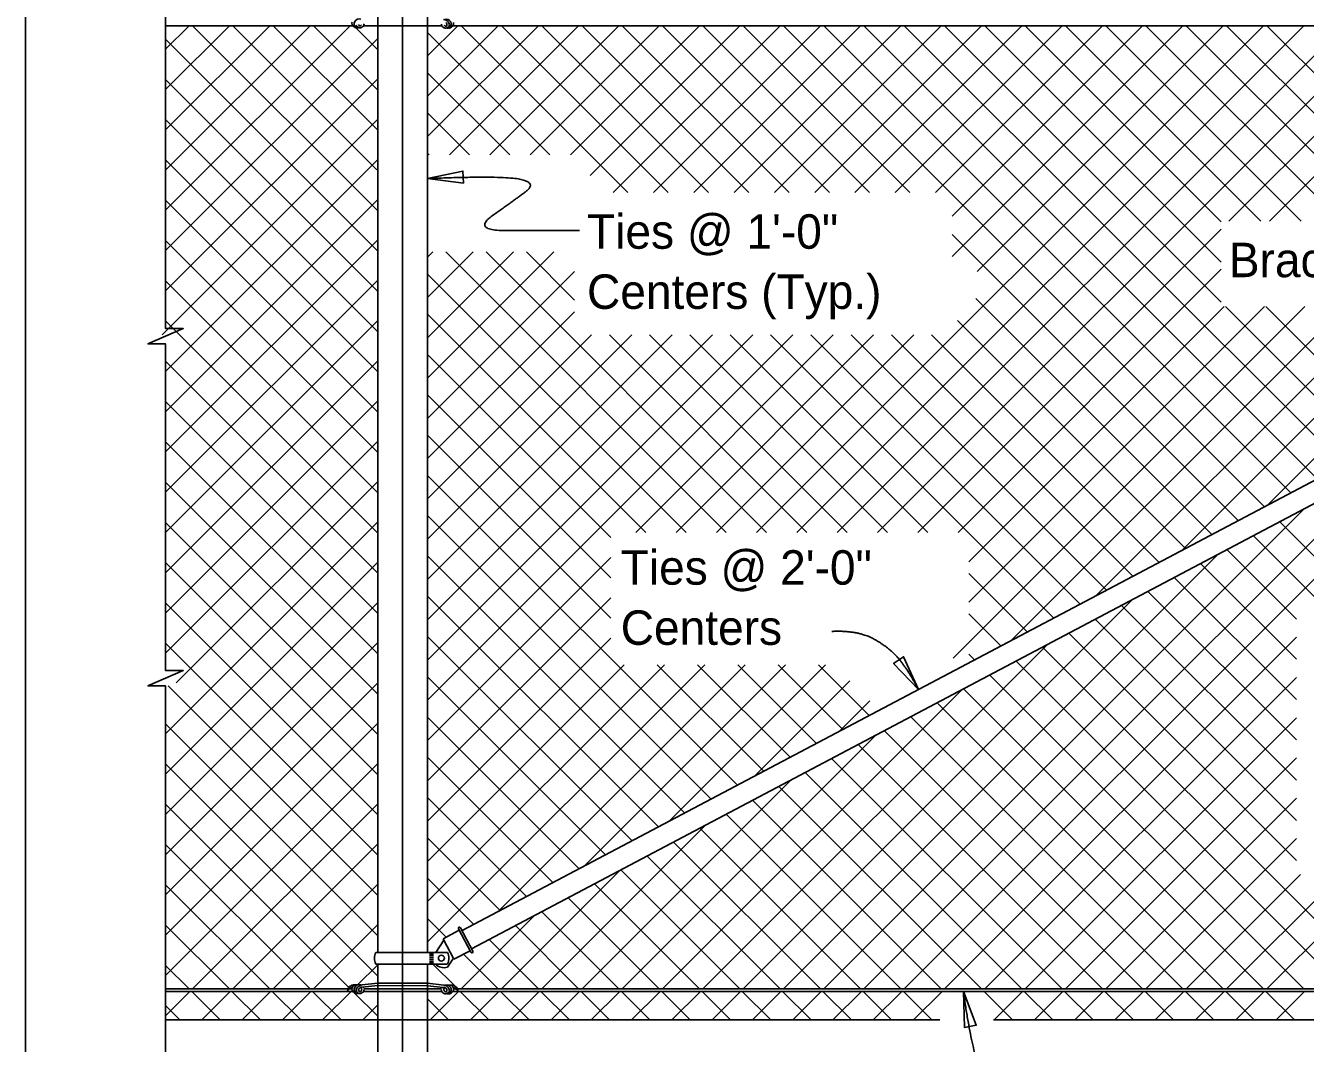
# Model space of a CAD drawing. Extents: x 0 to 41.2, y 0 to 26.
# Drawn here: x 0 to 7.49, y 17 to 22.96 of the extents above; entities that cross this region are included whole.
import ezdxf

# ---------------------------------------------------------------- set-up
doc = ezdxf.new("R2010")
doc.units = 0
for name, color, linetype in [('ActivePts-ConstElements', 7, 'Continuous'), ('CL_Major', 7, 'Continuous'), ('Dimension', 7, 'Continuous'), ('Miscellaneous', 7, 'Continuous'), ('Miscellaneous1', 7, 'Continuous'), ('SteelMisc', 7, 'Continuous'), ('SteelMisc_h', 7, 'Continuous'), ('SupstrConc', 7, 'Continuous'), ('TextStructures', 7, 'Continuous')]:
    doc.layers.add(name, color=color, linetype=linetype)

msp = doc.modelspace()

# ---------------------------------------------------------------- linework, layer by layer
at = {"layer": 'ActivePts-ConstElements'}
msp.add_lwpolyline([(0, 0), (41.2106, 0), (41.2106, 25.96), (0, 25.96)], close=True, dxfattribs=at)
at = {"layer": 'CL_Major'}
msp.add_line((2.2062, 25.5043), (2.2062, 14.6639), dxfattribs=at)
at = {"layer": 'Dimension'}
for points in [[(0.8194, 23.1382), (0.8194, 21.1819), (0.9227, 21.1819), (0.8194, 21.1369), (0.716, 21.0919), (0.8194, 21.0919), (0.8194, 20.1983)], [(0.8194, 20.1983), (0.8194, 19.1806), (0.9227, 19.1806), (0.8194, 19.1356), (0.716, 19.0906), (0.8194, 19.0906), (0.8194, 16.8862)], [(0.8194, 17.1362), (0.8194, 15.2854), (0.9227, 15.2854), (0.8194, 15.2404), (0.716, 15.1954), (0.8194, 15.1954), (0.8194, 13.3576)]]:
    msp.add_lwpolyline(points, dxfattribs=at)
for points in [[(2.3519, 22.0601), (2.5585, 22.1039), (2.5614, 22.0334)], [(5.2237, 19.0693), (5.1367, 19.2617), (5.0782, 19.2224)], [(5.4878, 17.3029), (5.4928, 17.0917), (5.5621, 17.1051)]]:
    msp.add_lwpolyline(points, close=True, dxfattribs=at)
for points in [[(3.2402, 21.7554), (3.0279, 21.7554), (2.6079, 21.7554), (2.8581, 21.9325), (2.9953, 22.0352), (2.7847, 22.0777), (2.352, 22.06)], [(4.7176, 19.4097), (4.8713, 19.4171), (5.0618, 19.3098), (5.1749, 19.1668), (5.2237, 19.0692)], [(6.1508, 16.5088), (5.753, 16.5088), (5.549, 16.8458), (5.4877, 17.3027)]]:
    msp.add_open_spline(points, degree=2, dxfattribs=at)
at = {"layer": 'Miscellaneous'}
for p, q in [((1.8998, 22.9547), (0.8192, 21.8742)), ((1.6641, 22.9547), (0.8192, 22.1099)), ((1.1927, 22.9547), (0.8192, 22.5813)), ((1.4284, 22.9547), (0.8192, 22.3456)), ((0.957, 22.9547), (0.8192, 22.817)), ((2.0603, 21.871), (0.9766, 22.9547)), ((2.0559, 22.1112), (1.2123, 22.9547)), ((2.0603, 22.3424), (1.448, 22.9547)), ((2.0603, 22.5781), (1.6837, 22.9547)), ((2.0603, 22.8138), (1.9308, 22.9433)), ((3.0002, 22.9547), (2.352, 22.3064)), ((2.7645, 22.9547), (2.352, 22.5421)), ((2.5288, 22.9547), (2.352, 22.7779)), ((3.0682, 22.1994), (2.352, 22.9155)), ((3.2359, 22.9547), (2.4806, 22.1994)), ((3.5244, 21.9789), (2.5485, 22.9547)), ((3.4716, 22.9547), (2.7163, 22.1994)), ((3.7601, 21.9789), (2.7842, 22.9547)), ((3.7073, 22.9547), (2.952, 22.1994)), ((3.9958, 21.9789), (3.0199, 22.9547)), ((3.943, 22.9547), (3.1877, 22.1994)), ((4.2315, 21.9789), (3.2556, 22.9547)), ((4.1788, 22.9547), (3.303, 22.0789)), ((4.4145, 22.9547), (3.4386, 21.9789)), ((4.4672, 21.9789), (3.4913, 22.9547)), ((4.6502, 22.9547), (3.6743, 21.9789)), ((4.7029, 21.9789), (3.727, 22.9547)), ((4.8859, 22.9547), (3.91, 21.9789)), ((4.9386, 21.9789), (3.9627, 22.9547)), ((5.1216, 22.9547), (4.1457, 21.9789)), ((5.1743, 21.9789), (4.1984, 22.9547)), ((7.2429, 22.9547), (4.2774, 19.9892)), ((5.3573, 22.9547), (4.3814, 21.9789)), ((7.2492, 20.1396), (4.4341, 22.9547)), ((7.4786, 22.9547), (4.5131, 19.9892)), ((5.593, 22.9547), (4.6171, 21.9789)), ((7.4034, 20.2211), (4.6698, 22.9547)), ((7.7143, 22.9547), (4.7488, 19.9892)), ((5.8287, 22.9547), (4.8528, 21.9789)), ((7.5576, 20.3026), (4.9055, 22.9547)), ((7.95, 22.9547), (4.9845, 19.9892)), ((6.0644, 22.9547), (5.0885, 21.9789)), ((7.7118, 20.3841), (5.1412, 22.9547)), ((6.3001, 22.9547), (5.3242, 21.9789)), ((6.9957, 21.336), (5.377, 22.9547)), ((6.5358, 22.9547), (5.4205, 21.8394)), ((6.7715, 22.9547), (5.4205, 21.6037)), ((7.0072, 22.9547), (5.5678, 21.5153)), ((6.9957, 21.5717), (5.6127, 22.9547)), ((6.9957, 21.8074), (5.8484, 22.9547)), ((7.2277, 21.811), (6.0841, 22.9547)), ((7.4634, 21.811), (6.3198, 22.9547)), ((7.6991, 21.811), (6.5555, 22.9547)), ((7.9348, 21.811), (6.7912, 22.9547)), ((8.1705, 21.811), (7.0269, 22.9547)), ((8.1857, 22.9547), (7.041, 21.81)), ((8.4062, 21.811), (7.2626, 22.9547)), ((8.4214, 22.9547), (7.2777, 21.811)), ((2.0603, 22.8796), (0.8192, 21.6385)), ((2.0603, 21.6353), (0.8192, 22.8764)), ((2.0603, 22.6439), (0.8192, 21.4028)), ((2.0603, 21.3996), (0.8192, 22.6407)), ((2.8325, 22.1994), (2.352, 22.6798)), ((2.0603, 22.4082), (0.7982, 21.146)), ((2.0603, 21.1639), (0.8192, 22.405)), ((2.5968, 22.1994), (2.352, 22.4441)), ((2.0603, 22.1725), (0.8192, 20.9314)), ((2.0603, 20.9282), (0.8192, 22.1693)), ((2.3611, 22.1994), (2.352, 22.2084)), ((2.0603, 21.9368), (0.8192, 20.6957)), ((2.0603, 20.6925), (0.8192, 21.9336)), ((6.9957, 21.7647), (5.2202, 19.9892)), ((7.095, 20.0581), (5.4205, 21.7327)), ((2.0603, 21.701), (0.8192, 20.46)), ((2.0603, 20.4568), (0.8192, 21.6979)), ((2.6187, 21.6304), (2.352, 21.3636)), ((2.383, 21.6304), (2.352, 21.5993)), ((2.8544, 21.6304), (2.352, 21.1279)), ((3.0901, 21.6304), (2.352, 20.8922)), ((4.0998, 19.9892), (2.4587, 21.6304)), ((4.3355, 19.9892), (2.6944, 21.6304)), ((3.2122, 21.3482), (2.9301, 21.6304)), ((3.2122, 21.5167), (2.352, 20.6565)), ((3.8641, 19.9892), (2.352, 21.5013)), ((6.9957, 21.529), (5.4559, 19.9892)), ((2.0603, 21.4653), (0.8192, 20.2243)), ((2.0603, 20.2211), (0.8192, 21.4622)), ((6.9408, 19.9766), (5.559, 21.3585)), ((3.2122, 21.281), (2.352, 20.4208)), ((7.4843, 21.3105), (5.4275, 19.2537)), ((7.0129, 21.3105), (5.5188, 19.8164)), ((7.2486, 21.3105), (5.5188, 19.5807)), ((7.72, 21.3105), (5.7646, 19.3551)), ((7.9557, 21.3105), (6.2644, 19.6192)), ((8.1914, 21.3105), (6.7643, 19.8834)), ((7.8661, 20.4656), (7.0212, 21.3105)), ((8.0203, 20.5471), (7.2569, 21.3105)), ((8.4271, 21.3105), (7.2641, 20.1475)), ((2.0603, 21.2296), (0.8192, 19.9886)), ((2.0603, 19.9854), (0.8192, 21.2265)), ((3.6284, 19.9892), (2.352, 21.2656)), ((6.7866, 19.8952), (5.4525, 21.2292)), ((4.2544, 21.1447), (2.352, 19.2423)), ((3.783, 21.1447), (2.352, 19.7137)), ((3.3116, 21.1447), (2.352, 20.1851)), ((3.5473, 21.1447), (2.352, 19.9494)), ((4.0187, 21.1447), (2.352, 19.478)), ((4.4901, 21.1447), (2.352, 19.0066)), ((4.5712, 19.9892), (3.4157, 21.1447)), ((4.7258, 21.1447), (3.5703, 19.9892)), ((4.8069, 19.9892), (3.6514, 21.1447)), ((4.9615, 21.1447), (3.806, 19.9892)), ((5.0426, 19.9892), (3.8871, 21.1447)), ((5.1972, 21.1447), (4.0417, 19.9892)), ((5.2783, 19.9892), (4.1228, 21.1447)), ((6.0155, 19.4877), (4.3585, 21.1447)), ((6.1697, 19.5692), (4.5942, 21.1447)), ((6.324, 19.6507), (4.8299, 21.1447)), ((6.4782, 19.7322), (5.0656, 21.1447)), ((6.6324, 19.8137), (5.3013, 21.1447)), ((2.0603, 20.9939), (0.8192, 19.7529)), ((2.0603, 19.7497), (0.8192, 20.9908)), ((3.4233, 19.9586), (2.352, 21.0299)), ((2.0603, 20.7582), (0.8192, 19.5171)), ((2.0603, 19.514), (0.8192, 20.7551)), ((3.4233, 19.7229), (2.352, 20.7942)), ((8.4761, 20.6523), (5.1412, 17.3175)), ((2.0603, 20.5225), (0.8192, 19.2814)), ((2.0603, 19.2783), (0.8192, 20.5194)), ((3.4233, 19.4872), (2.352, 20.5585)), ((7.9762, 20.3882), (4.9055, 17.3175)), ((4.165, 18.5098), (2.352, 20.3228)), ((2.0603, 19.0426), (0.8192, 20.2837)), ((2.0603, 20.2868), (0.8817, 19.1083)), ((4.0108, 18.4283), (2.352, 20.0871)), ((7.4764, 20.1241), (4.6698, 17.3175)), ((2.0603, 20.0511), (0.8192, 18.81)), ((2.0603, 18.8069), (0.8192, 20.048)), ((7.8655, 19.5233), (7.3379, 20.0509)), ((7.6298, 19.5233), (7.1837, 19.9694)), ((3.8566, 18.3468), (2.352, 19.8514)), ((6.9765, 19.8599), (4.4341, 17.3175)), ((7.4353, 19.4821), (7.0295, 19.8879)), ((2.0603, 19.8154), (0.8192, 18.5743)), ((2.0603, 18.5712), (0.8192, 19.8123)), ((3.4233, 19.8423), (2.352, 18.7709)), ((7.4353, 19.2464), (6.8753, 19.8064)), ((5.8613, 19.4062), (5.5188, 19.7488)), ((7.4353, 19.0107), (6.7211, 19.7249)), ((7.4353, 18.775), (6.5669, 19.6435)), ((2.0603, 19.5797), (0.8192, 18.3386)), ((2.0603, 18.3355), (0.8192, 19.5766)), ((3.7024, 18.2653), (2.352, 19.6157)), ((3.4233, 19.6066), (2.352, 18.5352)), ((6.4767, 19.5958), (4.1984, 17.3175)), ((7.4353, 18.5393), (6.4127, 19.562)), ((5.7071, 19.3247), (5.5188, 19.5131)), ((7.4353, 18.3036), (6.2585, 19.4805)), ((7.4353, 18.0679), (6.1042, 19.399)), ((2.0603, 19.344), (0.8192, 18.1029)), ((2.0603, 18.0998), (0.8192, 19.3409)), ((3.5482, 18.1838), (2.352, 19.38)), ((3.4233, 19.3709), (2.352, 18.2995)), ((5.9769, 19.3317), (3.9627, 17.3175)), ((7.4353, 19.3759), (5.377, 17.3175)), ((5.5529, 19.2432), (5.5188, 19.2774)), ((7.95, 17.3175), (5.95, 19.3175)), ((3.7384, 19.2146), (2.352, 17.8281)), ((3.5027, 19.2146), (2.352, 18.0638)), ((3.9741, 19.2146), (2.352, 17.5924)), ((4.2098, 19.2146), (2.7654, 17.7701)), ((4.4455, 19.2146), (3.2653, 18.0343)), ((4.3192, 18.5913), (3.6959, 19.2146)), ((4.6812, 19.2146), (3.7651, 18.2985)), ((4.4734, 18.6728), (3.9317, 19.2146)), ((4.6277, 18.7543), (4.1674, 19.2146)), ((4.7819, 18.8357), (4.4031, 19.2146)), ((4.9361, 18.9172), (4.6388, 19.2146)), ((7.7143, 17.3175), (5.7958, 19.236)), ((2.0603, 19.1083), (0.8192, 17.8672)), ((3.394, 18.1023), (2.352, 19.1443)), ((4.8227, 19.1203), (4.265, 18.5626)), ((7.4353, 19.1402), (5.6127, 17.3175)), ((7.4786, 17.3175), (5.6416, 19.1545)), ((2.0603, 17.8641), (0.8339, 19.0905)), ((5.477, 19.0675), (3.727, 17.3175)), ((7.2429, 17.3175), (5.4874, 19.073)), ((4.9405, 19.0024), (4.7648, 18.8268)), ((7.0072, 17.3175), (5.3332, 18.9915)), ((2.0603, 18.8726), (0.8192, 17.6315)), ((3.2398, 18.0208), (2.352, 18.9086)), ((6.7715, 17.3175), (5.179, 18.91)), ((7.4353, 18.9045), (5.8484, 17.3175)), ((2.0603, 17.6284), (0.8192, 18.8695)), ((4.9772, 18.8034), (3.4913, 17.3175)), ((6.5358, 17.3175), (5.0248, 18.8285)), ((6.3001, 17.3175), (4.8706, 18.747)), ((3.0856, 17.9393), (2.352, 18.6729)), ((6.0644, 17.3175), (4.7163, 18.6656)), ((7.4353, 18.6688), (6.0841, 17.3175)), ((2.0603, 18.6369), (0.8192, 17.3958)), ((2.0603, 17.3927), (0.8192, 18.6338)), ((5.8287, 17.3175), (4.5621, 18.5841)), ((4.4774, 18.5393), (3.2556, 17.3175)), ((5.593, 17.3175), (4.4079, 18.5026)), ((2.9314, 17.8578), (2.352, 18.4372)), ((5.3573, 17.3175), (4.2537, 18.4211)), ((7.4353, 18.4331), (6.3198, 17.3175)), ((1.8909, 17.3264), (0.8192, 18.3981)), ((2.0603, 18.4012), (0.9766, 17.3175)), ((3.9775, 18.2751), (3.0199, 17.3175)), ((5.1216, 17.3175), (4.0995, 18.3396)), ((2.7771, 17.7763), (2.352, 18.2015)), ((4.8859, 17.3175), (3.9453, 18.2581)), ((7.4353, 18.1974), (6.5555, 17.3175)), ((1.6641, 17.3175), (0.8192, 18.1624)), ((2.0603, 18.1655), (1.2123, 17.3175)), ((4.6502, 17.3175), (3.7911, 18.1766)), ((4.4145, 17.3175), (3.6369, 18.0951)), ((3.4777, 18.011), (2.7842, 17.3175)), ((4.1788, 17.3175), (3.4827, 18.0136)), ((7.4598, 17.9862), (6.7912, 17.3175)), ((7.6955, 17.9862), (7.0269, 17.3175)), ((7.9312, 17.9862), (7.2626, 17.3175)), ((1.4284, 17.3175), (0.8192, 17.9267)), ((2.0603, 17.9298), (1.448, 17.3175)), ((2.6229, 17.6948), (2.352, 17.9658)), ((3.943, 17.3175), (3.3285, 17.9321)), ((3.7073, 17.3175), (3.1742, 17.8506)), ((3.4716, 17.3175), (3.02, 17.7692)), ((1.1927, 17.3175), (0.8192, 17.691)), ((2.0603, 17.6941), (1.6837, 17.3175)), ((2.4612, 17.6209), (2.352, 17.7301)), ((2.9778, 17.7469), (2.5485, 17.3175)), ((3.2359, 17.3175), (2.8658, 17.6877)), ((3.0002, 17.3175), (2.7116, 17.6062)), ((0.957, 17.3175), (0.8192, 17.4553)), ((2.0603, 17.4584), (1.9429, 17.341)), ((2.5129, 17.3335), (2.3833, 17.4631)), ((2.7645, 17.3175), (2.5621, 17.52)), ((0.9619, 17.3028), (0.8192, 17.1601)), ((1.1384, 17.1361), (0.9717, 17.3028)), ((1.1976, 17.3028), (1.0309, 17.1361)), ((1.3741, 17.1361), (1.2074, 17.3028)), ((1.4333, 17.3028), (1.2666, 17.1361)), ((1.6098, 17.1361), (1.4431, 17.3028)), ((1.669, 17.3028), (1.5023, 17.1361)), ((1.8455, 17.1361), (1.6788, 17.3028)), ((1.9047, 17.3028), (1.738, 17.1361)), ((2.5338, 17.3028), (2.3671, 17.1361)), ((2.5288, 17.3175), (2.5253, 17.3211)), ((2.7103, 17.1361), (2.5436, 17.3028)), ((2.7695, 17.3028), (2.6028, 17.1361)), ((2.946, 17.1361), (2.7793, 17.3028)), ((3.0052, 17.3028), (2.8385, 17.1361)), ((3.1817, 17.1361), (3.015, 17.3028)), ((3.2409, 17.3028), (3.0742, 17.1361)), ((3.4174, 17.1361), (3.2507, 17.3028)), ((3.4766, 17.3028), (3.3099, 17.1361)), ((3.6531, 17.1361), (3.4864, 17.3028)), ((3.7123, 17.3028), (3.5456, 17.1361)), ((3.8888, 17.1361), (3.7221, 17.3028)), ((3.948, 17.3028), (3.7813, 17.1361)), ((4.1245, 17.1361), (3.9578, 17.3028)), ((4.1837, 17.3028), (4.017, 17.1361)), ((4.3602, 17.1361), (4.1935, 17.3028)), ((4.4194, 17.3028), (4.2527, 17.1361)), ((4.5959, 17.1361), (4.4292, 17.3028)), ((4.6551, 17.3028), (4.4884, 17.1361)), ((4.8316, 17.1361), (4.6649, 17.3028)), ((4.8908, 17.3028), (4.7241, 17.1361)), ((5.0673, 17.1361), (4.9006, 17.3028)), ((5.1265, 17.3028), (4.9598, 17.1361)), ((5.303, 17.1361), (5.1363, 17.3028)), ((5.3622, 17.3028), (5.1955, 17.1361)), ((5.7744, 17.1361), (5.6077, 17.3028)), ((5.8336, 17.3028), (5.6669, 17.1361)), ((6.0101, 17.1361), (5.8434, 17.3028)), ((6.0693, 17.3028), (5.9026, 17.1361)), ((6.2458, 17.1361), (6.0791, 17.3028)), ((6.305, 17.3028), (6.1383, 17.1361)), ((6.4815, 17.1361), (6.3148, 17.3028)), ((6.5407, 17.3028), (6.374, 17.1361)), ((6.7172, 17.1361), (6.5505, 17.3028)), ((6.7764, 17.3028), (6.6097, 17.1361)), ((6.9529, 17.1361), (6.7862, 17.3028)), ((7.0121, 17.3028), (6.8455, 17.1361)), ((7.1886, 17.1361), (7.0219, 17.3028)), ((7.2478, 17.3028), (7.0812, 17.1361)), ((7.4243, 17.1361), (7.2576, 17.3028)), ((7.4835, 17.3028), (7.3169, 17.1361)), ((2.0603, 17.157), (1.922, 17.2953)), ((2.4746, 17.1361), (2.352, 17.2587)), ((0.9027, 17.1361), (0.8192, 17.2196)), ((2.0571, 17.2195), (1.9737, 17.1361))]:
    msp.add_line(p, q, dxfattribs=at)
at = {"layer": 'Miscellaneous1'}
msp.add_lwpolyline([(0, 25.96), (41.2106, 25.96), (41.2106, 0), (0, 0)], close=True, dxfattribs=at)
at = {"layer": 'SteelMisc'}
for p, q in [((2.0603, 17.5309), (2.0603, 23.1761)), ((2.352, 17.5309), (2.352, 23.1761)), ((1.9145, 22.9547), (0.8192, 22.9547)), ((2.0603, 22.9547), (1.9773, 22.9547)), ((2.4356, 22.9547), (2.352, 22.9547)), ((11.9243, 22.9547), (2.5005, 22.9547)), ((2.5536, 17.6582), (11.8032, 22.5462)), ((2.6095, 17.5522), (11.8592, 22.4401)), ((2.6171, 17.538), (2.5446, 17.6751)), ((2.4468, 17.6031), (2.3999, 17.5313)), ((2.5369, 17.6609), (2.4426, 17.6111)), ((2.5063, 17.4905), (2.4426, 17.6111)), ((2.6052, 17.5317), (2.5328, 17.6688)), ((2.049, 17.5309), (2.4687, 17.5309)), ((2.3864, 17.5246), (2.3629, 17.5246)), ((2.5063, 17.4905), (2.6006, 17.5404)), ((2.0491, 17.4631), (2.4687, 17.4631)), ((2.0603, 16.801), (2.0603, 17.4631)), ((2.352, 16.801), (2.352, 17.4631)), ((2.3864, 17.5148), (2.3629, 17.5148)), ((2.3864, 17.5031), (2.3629, 17.5031)), ((2.3864, 17.4913), (2.3629, 17.4913)), ((2.3864, 17.4805), (2.3629, 17.4805)), ((2.3864, 17.4709), (2.3629, 17.4709)), ((2.5029, 17.4971), (2.4681, 17.4439)), ((1.8859, 17.3175), (0.8192, 17.3175)), ((1.9154, 17.3028), (0.8192, 17.3028)), ((1.9096, 17.3175), (1.8943, 17.3175)), ((2.0608, 17.3518), (1.9665, 17.3407)), ((2.0608, 17.3373), (1.9687, 17.3279)), ((2.0603, 17.3028), (1.9773, 17.3028)), ((2.0603, 17.3175), (1.9799, 17.3175)), ((2.352, 17.3501), (2.0608, 17.3518)), ((2.352, 17.3356), (2.0608, 17.3373)), ((2.352, 17.3501), (2.4469, 17.339)), ((2.352, 17.3356), (2.4446, 17.3261)), ((2.4342, 17.3175), (2.352, 17.3175)), ((2.4356, 17.3028), (2.352, 17.3028)), ((11.8982, 17.3028), (2.5005, 17.3028)), ((2.5172, 17.3175), (2.5041, 17.3175)), ((11.8969, 17.3175), (2.5271, 17.3175))]:
    msp.add_line(p, q, dxfattribs=at)
for centre, start, end in [((2.5385, 17.6721), 27.85098, 207.85098), ((2.611, 17.5349), 207.85098, 27.85098)]:
    msp.add_arc(centre, 0.00673, start, end, dxfattribs=at)
for centre, major_axis, ratio, start_param, end_param in [((1.9521, 22.9661), (0.0295, 0), 0.957868, 1.220941, 4.039556), ((2.4482, 22.9661), (0.0303, -0.0108), 0.724765, 6.241815, 8.212701), ((2.4617, 22.9643), (-0.0295, 0), 0.957868, 2.243629, 5.062245), ((1.9345, 22.9689), (-0.0249, 0), 0.957868, 6.009018, 7.089857), ((1.9359, 22.9649), (0.0231, 0), 0.957868, 3.779554, 4.879821), ((1.942, 22.9592), (0.0206, -0.0021), 0.798607, 4.32653, 5.220153), ((1.9554, 22.9592), (0.0206, -0.0021), 0.798607, 3.333154, 5.220153), ((1.9566, 22.9614), (-0.00795, 0), 0.957868, 6.140374, 9.314262), ((1.9481, 22.978), (0.0391, 0), 0.957868, 5.082588, 5.41974), ((1.9551, 22.966), (0.0251, 0), 0.957868, 5.531357, 6.227833), ((2.4586, 22.9642), (-0.0251, 0), 0.957868, 0.055352, 0.751829), ((2.4657, 22.9762), (-0.0391, 0), 0.957868, 0.863445, 1.200597), ((2.4572, 22.9596), (0.00795, 0), 0.957868, 3.252108, 6.425997), ((2.4583, 22.9575), (-0.0206, -0.0021), 0.798607, 1.063032, 2.950031), ((2.4515, 22.962), (0.0139, 0), 0.957868, 5.660958, 7.342751), ((2.4718, 22.9575), (-0.0206, -0.0021), 0.798607, 1.063032, 1.956656), ((2.4779, 22.9631), (-0.0231, 0), 0.957868, 1.403365, 2.503632), ((2.4793, 22.9671), (0.0249, 0), 0.957868, 5.476514, 6.557353), ((2.1181, 17.4971), (-0.0776, 0), 0.957868, 5.811591, 6.758603), ((2.3995, 17.4972), (0.0776, 0), 0.957868, 5.810211, 6.75616), ((2.4515, 17.5123), (-0.0647, -0.0342), 0.957868, 0.271397, 1.331255), ((1.9209, 17.305), (0.0373, 0), 0.957868, 1.486836, 3.108042), ((1.942, 17.2653), (-0.0724, 0), 0.957868, 5.162149, 5.652106), ((1.9345, 17.317), (-0.0249, 0), 0.957868, 6.009018, 7.089857), ((1.9333, 17.3195), (0.023, 0), 0.957868, 1.29026, 2.970541), ((1.9359, 17.313), (0.0231, 0), 0.957868, 3.779554, 4.879821), ((1.9521, 17.3141), (0.0295, 0), 0.957868, 1.220941, 4.039556), ((1.9656, 17.3159), (-0.0303, -0.0108), 0.724765, 4.35367, 6.324556), ((1.9554, 17.3073), (0.0206, -0.0021), 0.798607, 3.333154, 5.220153), ((1.9623, 17.3119), (-0.0139, 0), 0.957868, 5.22362, 6.905413), ((1.9566, 17.3095), (-0.00795, 0), 0.957868, 6.140374, 9.314262), ((1.9706, 17.303), (-0.0259, 0), 0.957868, 4.777514, 5.62749), ((1.9549, 17.3153), (0.0119, 0), 0.957868, 5.725876, 7.416677), ((1.9549, 17.3153), (0.0119, 0), 0.957868, 5.639684, 5.723117), ((1.9551, 17.314), (0.0251, 0), 0.957868, 5.531357, 6.227833), ((1.9551, 17.314), (0.0251, 0), 0.957868, 0.407687, 0.609214), ((2.4586, 17.3123), (-0.0251, 0), 0.957868, 0.055352, 0.751829), ((2.4586, 17.3123), (-0.0251, 0), 0.957868, 5.673972, 5.875498), ((2.4431, 17.3012), (0.0259, 0), 0.957868, 0.655696, 1.505671), ((2.4482, 17.3142), (0.0303, -0.0108), 0.724765, 6.241815, 8.212701), ((2.4589, 17.3135), (-0.0119, 0), 0.957868, 5.149694, 6.840495), ((2.4589, 17.3135), (-0.0119, 0), 0.957868, 0.560069, 0.643501), ((2.4572, 17.3077), (0.00795, 0), 0.957868, 3.252108, 6.425997), ((2.4583, 17.3055), (-0.0206, -0.0021), 0.798607, 1.063032, 2.950031), ((2.4617, 17.3124), (-0.0295, 0), 0.957868, 2.243629, 5.062245), ((2.4515, 17.3101), (0.0139, 0), 0.957868, 5.660958, 7.342751), ((2.4804, 17.3177), (-0.023, 0), 0.957868, 3.312645, 4.992926), ((2.4779, 17.3112), (-0.0231, 0), 0.957868, 1.403365, 2.503632), ((2.4929, 17.3033), (-0.0373, 0), 0.957868, 3.175144, 4.79635), ((2.4793, 17.3152), (0.0249, 0), 0.957868, 5.476514, 6.557353), ((2.4718, 17.2636), (0.0724, 0), 0.957868, 0.631079, 1.121037), ((1.942, 17.3073), (0.0206, -0.0021), 0.798607, 4.32653, 5.220153), ((1.9481, 17.3261), (0.0391, 0), 0.957868, 5.082588, 5.41974), ((2.4657, 17.3243), (-0.0391, 0), 0.957868, 0.863445, 1.200597), ((2.4718, 17.3055), (-0.0206, -0.0021), 0.798607, 1.063032, 1.956656)]:
    msp.add_ellipse(centre, major_axis=major_axis, ratio=ratio, start_param=start_param, end_param=end_param, dxfattribs=at)
msp.add_ellipse((2.4328, 17.4976), major_axis=(-0.0178, 0), ratio=0.957868, dxfattribs=at)
at = {"layer": 'SteelMisc_h'}
for p, q in [((2.352, 22.9547), (2.0603, 22.9547)), ((2.352, 17.3175), (2.0603, 17.3175)), ((2.352, 17.3028), (2.0603, 17.3028))]:
    msp.add_line(p, q, dxfattribs=at)
at = {"layer": 'SupstrConc'}
for p, q in [((0.8193, 17.1361), (5.3495, 17.1361)), ((5.6627, 17.1361), (12.0604, 17.1361))]:
    msp.add_line(p, q, dxfattribs=at)

# ---------------------------------------------------------------- texts
at = {"layer": 'TextStructures'}
for s, p in [('Ties @ 1\'-0" ', (3.285, 21.6493)), ('Brace Rail', (7.0402, 21.4829)), ('Centers (Typ.)', (3.285, 21.2973)), ('Ties @ 2\'-0" ', (3.4821, 19.6831)), ('Centers', (3.4821, 19.3311))]:
    msp.add_text(s, height=0.2016, dxfattribs=at).set_placement(p)

doc.saveas('drawing.dxf')
